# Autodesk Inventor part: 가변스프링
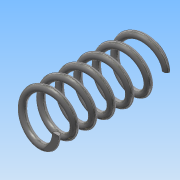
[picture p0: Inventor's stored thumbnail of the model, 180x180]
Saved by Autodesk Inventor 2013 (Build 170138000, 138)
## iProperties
Created: 2015-05
Part Number: 가변스프링
Material: 강철, 탄소
Document SubType Name: Modeling
Designer: Administrator
Density: 7.87 g/cm^3
Mass: 11.4967 g
Surface Area: 23.7324 cm^2
Volume: 1.46083 cm^3
Author: Administrator
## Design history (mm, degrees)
sketch "스케치1"
  geometry: L1 (0, 0)-(8, 0); L2 (8, 0)-(8, 42); L3 (8, 42)-(0, 42); L4 (0, 42)-(0, 0); C1 r 1.25 at (8, 0)
  constraints: 8 end point, 2 parallel, 1 centre point, 1 coincident, 1 horizontal, 1 perpendicular
  dimensions: "d0" = 42 distance of L3.end L1.start (derived); "d1" = 16 diameter of L2 L4; "d2" = 2.5 diameter of C1
feature "코일1" sketch "스케치1" pitch "d3" = 10; turns "d5" = 6; dims "d4" = 42 (= d0), "d6" = 0, angle "d7" = 90 deg, angle "d8" = 90 deg, "d9" = 0, "d10" = 0
sketch "스케치2"
  geometry: L1 (0, 12.5)-(42, 12.5); L2 (42, 12.5)-(42, -12.5); L3 (42, -12.5)-(0, -12.5); L4 (0, -12.5)-(0, 12.5); 4 further points
  constraints: 8 end point, 2 coincident, 2 midpoint, 2 parallel, 1 horizontal, 1 perpendicular
  dimensions: "d11" = 42 distance of L2.end L3.end (derived); "d12" = 25 distance of L1.end L2.end
extrude "돌출1" sketch "스케치2" stored distance "d13" = 10; taper "d14" = 0 deg
node "솔리드1"
